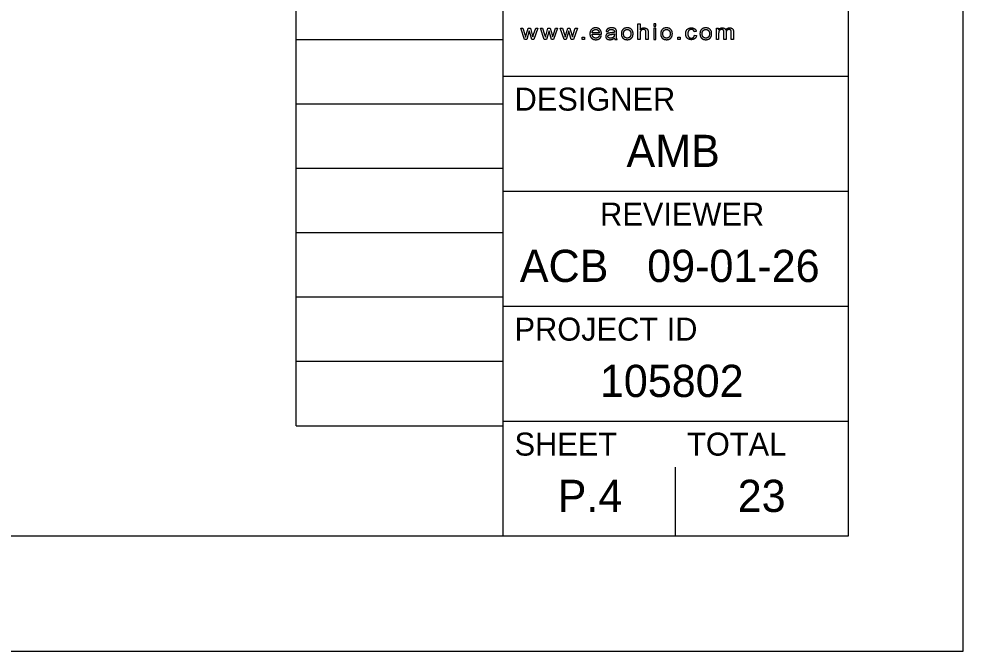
# Model space of a CAD drawing. Extents: x 0 to 34, y 0 to 22.
# Drawn here: x 29.895 to 34, y 0 to 2.749 of the extents above; entities that cross this region are included whole.
import ezdxf

# ---------------------------------------------------------------- set-up
doc = ezdxf.new("R2010")
doc.units = 0
for name, color, linetype in [('SH_Border', 7, 'Continuous'), ('SH_Cut_Line', 7, 'Continuous'), ('SH_Data', 7, 'Continuous'), ('TX_X_20', 7, 'Continuous')]:
    doc.layers.add(name, color=color, linetype=linetype)

msp = doc.modelspace()

# ---------------------------------------------------------------- linework, layer by layer
at = {"layer": 'SH_Border'}
for p, q in [((32, 0.5), (32, 21.5)), ((32, 2.5), (33.5, 2.5)), ((32, 2), (33.5, 2)), ((32, 1.5), (33.5, 1.5)), ((32, 1), (33.5, 1))]:
    msp.add_line(p, q, dxfattribs=at)
msp.add_lwpolyline([(1.5, 21.5), (33.5, 21.5), (33.5, 0.5), (1.5, 0.5)], close=True, dxfattribs=at)
at = {"layer": 'SH_Cut_Line'}
msp.add_lwpolyline([(0, 0), (34, 0), (34, 22), (0, 22)], close=True, dxfattribs=at)
at = {"layer": 'SH_Data'}
for p, q in [((31.1, 0.98), (31.1, 21.14)), ((32, 0.98), (32, 21.14)), ((31.1, 2.66), (32, 2.66)), ((31.1, 2.38), (32, 2.38)), ((31.1, 2.1), (32, 2.1)), ((31.1, 1.82), (32, 1.82)), ((31.1, 1.54), (32, 1.54)), ((31.1, 1.26), (32, 1.26)), ((31.1, 0.98), (32, 0.98)), ((32.75, 0.5), (32.75, 0.8)), ((32.375, 0.675), (32.375, 0.675))]:
    msp.add_line(p, q, dxfattribs=at)
at = {"layer": 'TX_X_20'}
for p, q in [((32.387, 2.6821), (32.4274, 2.6821)), ((32.4178, 2.6889), (32.3875, 2.6889)), ((32.4272, 2.6744), (32.4177, 2.6755)), ((32.4477, 2.6948), (32.4567, 2.6937)), ((32.4838, 2.6843), (32.4838, 2.6812)), ((32.4931, 2.6802), (32.4931, 2.6913)), ((32.5143, 2.6842), (32.5143, 2.6842)), ((32.5238, 2.6842), (32.5238, 2.6842)), ((32.6852, 2.6842), (32.6852, 2.6842)), ((32.6946, 2.6842), (32.6946, 2.6842)), ((32.8402, 2.6944), (32.8313, 2.6931)), ((32.8321, 2.6776), (32.8411, 2.6765)), ((32.856, 2.6842), (32.856, 2.6842)), ((32.8655, 2.6842), (32.8655, 2.6842)), ((32.4846, 2.6656), (32.4846, 2.6656)), ((32.4864, 2.6596), (32.496, 2.6596))]:
    msp.add_line(p, q, dxfattribs=at)
for points in [[(32.5955, 2.6865), (32.5955, 2.6596), (32.5863, 2.6596), (32.5863, 2.7276), (32.5955, 2.7276), (32.5955, 2.7032)], [(32.1007, 2.68), (32.1093, 2.7089), (32.1188, 2.7089), (32.1269, 2.6802), (32.1295, 2.6708), (32.1327, 2.6804), (32.142, 2.7089), (32.1509, 2.7089), (32.1339, 2.6596), (32.1244, 2.6596), (32.1158, 2.6891), (32.1137, 2.6975), (32.1027, 2.6596), (32.0931, 2.6596), (32.0766, 2.7089), (32.0861, 2.7089), (32.0947, 2.6804), (32.0979, 2.6698)], [(32.1867, 2.68), (32.1953, 2.7089), (32.2048, 2.7089), (32.2129, 2.6802), (32.2155, 2.6708), (32.2186, 2.6804), (32.228, 2.7089), (32.2369, 2.7089), (32.2199, 2.6596), (32.2104, 2.6596), (32.2018, 2.6891), (32.1997, 2.6975), (32.1886, 2.6596), (32.179, 2.6596), (32.1625, 2.7089), (32.172, 2.7089), (32.1807, 2.6804), (32.1838, 2.6698)], [(32.2726, 2.68), (32.2813, 2.7089), (32.2907, 2.7089), (32.2988, 2.6802), (32.3015, 2.6708), (32.3046, 2.6804), (32.3139, 2.7089), (32.3229, 2.7089), (32.3059, 2.6596), (32.2964, 2.6596), (32.2878, 2.6891), (32.2856, 2.6975), (32.2746, 2.6596), (32.265, 2.6596), (32.2485, 2.7089), (32.258, 2.7089), (32.2666, 2.6804), (32.2698, 2.6698)], [(32.6305, 2.6908), (32.6305, 2.6596), (32.6213, 2.6596), (32.6213, 2.6908)], [(32.9372, 2.6851), (32.9372, 2.6596), (32.928, 2.6596), (32.928, 2.7089), (32.9362, 2.7089), (32.9362, 2.7019)], [(32.9694, 2.6882), (32.9694, 2.6596), (32.9602, 2.6596), (32.9602, 2.6916)], [(33.0015, 2.6934), (33.0015, 2.6596), (32.9923, 2.6596), (32.9923, 2.6906)]]:
    msp.add_lwpolyline(points, dxfattribs=at)
for points in [[(32.655, 2.718), (32.6642, 2.718), (32.6642, 2.7276), (32.655, 2.7276)], [(32.3437, 2.6596), (32.3437, 2.669), (32.3541, 2.669), (32.3541, 2.6596)], [(32.655, 2.6596), (32.6642, 2.6596), (32.6642, 2.7089), (32.655, 2.7089)], [(32.7597, 2.6596), (32.7597, 2.669), (32.7702, 2.669), (32.7702, 2.6596)]]:
    msp.add_lwpolyline(points, close=True, dxfattribs=at)
for points in [[(32.4028, 2.71), (32.3916, 2.71), (32.3846, 2.7031)], [(32.4206, 2.7032), (32.4137, 2.71), (32.4028, 2.71)], [(32.4721, 2.71), (32.4651, 2.71), (32.4598, 2.7082)], [(32.4834, 2.7085), (32.479, 2.71), (32.4721, 2.71)], [(32.5398, 2.71), (32.5297, 2.71), (32.5227, 2.7045)], [(32.558, 2.7033), (32.5509, 2.71), (32.5398, 2.71)], [(32.5955, 2.7032), (32.602, 2.71), (32.6118, 2.71)], [(32.6118, 2.71), (32.6178, 2.71), (32.6222, 2.7078)], [(32.7106, 2.71), (32.7005, 2.71), (32.6935, 2.7045)], [(32.7288, 2.7033), (32.7218, 2.71), (32.7106, 2.71)], [(32.8056, 2.707), (32.8116, 2.71), (32.8186, 2.71)], [(32.8186, 2.71), (32.8274, 2.71), (32.833, 2.7059)], [(32.8814, 2.71), (32.8714, 2.71), (32.8644, 2.7045)], [(32.8997, 2.7033), (32.8926, 2.71), (32.8814, 2.71)], [(32.943, 2.7077), (32.9472, 2.71), (32.9527, 2.71)], [(32.9527, 2.71), (32.9587, 2.71), (32.9625, 2.7077)], [(32.968, 2.7013), (32.9744, 2.71), (32.9847, 2.71)], [(32.9847, 2.71), (32.9928, 2.71), (32.9972, 2.7059)], [(32.0979, 2.6698), (32.0981, 2.6706), (32.1007, 2.68)], [(32.1838, 2.6698), (32.184, 2.6706), (32.1867, 2.68)], [(32.2698, 2.6698), (32.27, 2.6706), (32.2726, 2.68)], [(32.3846, 2.7031), (32.3775, 2.6962), (32.3775, 2.6838)], [(32.3775, 2.6838), (32.3775, 2.6718), (32.3845, 2.6651)], [(32.3921, 2.6696), (32.3875, 2.6739), (32.387, 2.6821)], [(32.3875, 2.6889), (32.388, 2.6954), (32.3923, 2.6992)], [(32.4034, 2.6653), (32.3966, 2.6653), (32.3921, 2.6696)], [(32.3923, 2.6992), (32.3966, 2.7031), (32.4029, 2.7031)], [(32.4029, 2.7031), (32.4099, 2.7031), (32.4143, 2.6983)], [(32.4177, 2.6755), (32.4156, 2.6702), (32.412, 2.6677)], [(32.4143, 2.6983), (32.4172, 2.6951), (32.4178, 2.6889)], [(32.4189, 2.6626), (32.4249, 2.6668), (32.4272, 2.6744)], [(32.4275, 2.6843), (32.4275, 2.6965), (32.4206, 2.7032)], [(32.4274, 2.6821), (32.4275, 2.6835), (32.4275, 2.6843)], [(32.4479, 2.6792), (32.4461, 2.6762), (32.4461, 2.6726)], [(32.4461, 2.6726), (32.4461, 2.6664), (32.4509, 2.6624)], [(32.4517, 2.7032), (32.4489, 2.7), (32.4477, 2.6948)], [(32.4526, 2.684), (32.4497, 2.6822), (32.4479, 2.6792)], [(32.4598, 2.7082), (32.4545, 2.7065), (32.4517, 2.7032)], [(32.4592, 2.6867), (32.4555, 2.6858), (32.4526, 2.684)], [(32.4559, 2.6728), (32.4559, 2.675), (32.4571, 2.6768)], [(32.4586, 2.6672), (32.4559, 2.6695), (32.4559, 2.6728)], [(32.4567, 2.6937), (32.4581, 2.6989), (32.4612, 2.701)], [(32.4571, 2.6768), (32.4584, 2.6785), (32.4608, 2.6795)], [(32.4674, 2.688), (32.4619, 2.6873), (32.4592, 2.6867)], [(32.4608, 2.6795), (32.4631, 2.6804), (32.4688, 2.6811)], [(32.4612, 2.701), (32.4643, 2.7031), (32.4708, 2.7031)], [(32.4838, 2.6908), (32.4785, 2.6892), (32.4674, 2.688)], [(32.4688, 2.6811), (32.4788, 2.6824), (32.4838, 2.6843)], [(32.4708, 2.7031), (32.4777, 2.7031), (32.4812, 2.7002)], [(32.4823, 2.6729), (32.4803, 2.6692), (32.4762, 2.6671)], [(32.4812, 2.7002), (32.4838, 2.6981), (32.4838, 2.693)], [(32.4838, 2.6812), (32.4838, 2.6757), (32.4823, 2.6729)], [(32.4897, 2.7047), (32.4877, 2.707), (32.4834, 2.7085)], [(32.4838, 2.693), (32.4838, 2.6925), (32.4838, 2.6908)], [(32.4926, 2.699), (32.4918, 2.7025), (32.4897, 2.7047)], [(32.4931, 2.6913), (32.4931, 2.6969), (32.4926, 2.699)], [(32.4936, 2.6655), (32.4931, 2.6686), (32.4931, 2.6802)], [(32.5227, 2.7045), (32.5143, 2.6979), (32.5143, 2.6842)], [(32.5143, 2.6842), (32.5143, 2.6717), (32.5214, 2.6651)], [(32.5238, 2.6842), (32.5238, 2.6937), (32.5283, 2.6984)], [(32.5283, 2.67), (32.5238, 2.6747), (32.5238, 2.6842)], [(32.5283, 2.6984), (32.5329, 2.7031), (32.5398, 2.7031)], [(32.5398, 2.6653), (32.5329, 2.6653), (32.5283, 2.67)], [(32.5398, 2.7031), (32.5465, 2.7031), (32.5511, 2.6983)], [(32.5511, 2.6701), (32.5466, 2.6653), (32.5398, 2.6653)], [(32.5511, 2.6983), (32.5556, 2.6936), (32.5556, 2.6845)], [(32.5556, 2.6845), (32.5556, 2.6748), (32.5511, 2.6701)], [(32.5528, 2.6615), (32.5588, 2.6645), (32.562, 2.67)], [(32.5651, 2.6849), (32.5651, 2.6966), (32.558, 2.7033)], [(32.562, 2.67), (32.5651, 2.6754), (32.5651, 2.6849)], [(32.5971, 2.6956), (32.5955, 2.6923), (32.5955, 2.6865)], [(32.6022, 2.7008), (32.5986, 2.6989), (32.5971, 2.6956)], [(32.6099, 2.7028), (32.6058, 2.7028), (32.6022, 2.7008)], [(32.6183, 2.6999), (32.6153, 2.7028), (32.6099, 2.7028)], [(32.6213, 2.6908), (32.6213, 2.697), (32.6183, 2.6999)], [(32.6222, 2.7078), (32.6267, 2.7056), (32.6286, 2.7018)], [(32.6286, 2.7018), (32.6305, 2.698), (32.6305, 2.6908)], [(32.6935, 2.7045), (32.6852, 2.6979), (32.6852, 2.6842)], [(32.6852, 2.6842), (32.6852, 2.6717), (32.6922, 2.6651)], [(32.6946, 2.6842), (32.6946, 2.6937), (32.6992, 2.6984)], [(32.6992, 2.67), (32.6946, 2.6747), (32.6946, 2.6842)], [(32.6992, 2.6984), (32.7037, 2.7031), (32.7106, 2.7031)], [(32.7106, 2.6653), (32.7037, 2.6653), (32.6992, 2.67)], [(32.7106, 2.7031), (32.7174, 2.7031), (32.7219, 2.6983)], [(32.7219, 2.6701), (32.7174, 2.6653), (32.7106, 2.6653)], [(32.7219, 2.6983), (32.7265, 2.6936), (32.7265, 2.6845)], [(32.7265, 2.6845), (32.7265, 2.6748), (32.7219, 2.6701)], [(32.7237, 2.6615), (32.7297, 2.6645), (32.7328, 2.67)], [(32.7359, 2.6849), (32.7359, 2.6966), (32.7288, 2.7033)], [(32.7328, 2.67), (32.7359, 2.6754), (32.7359, 2.6849)], [(32.7939, 2.684), (32.7939, 2.692), (32.7968, 2.698)], [(32.8006, 2.6651), (32.7939, 2.6717), (32.7939, 2.684)], [(32.7968, 2.698), (32.7997, 2.704), (32.8056, 2.707)], [(32.8077, 2.6986), (32.8033, 2.6941), (32.8033, 2.6843)], [(32.8033, 2.6843), (32.8033, 2.6743), (32.8075, 2.6698)], [(32.8075, 2.6698), (32.8117, 2.6653), (32.8185, 2.6653)], [(32.8189, 2.7031), (32.812, 2.7031), (32.8077, 2.6986)], [(32.8185, 2.6653), (32.8239, 2.6653), (32.8275, 2.6683)], [(32.8268, 2.7006), (32.8235, 2.7031), (32.8189, 2.7031)], [(32.8313, 2.6931), (32.83, 2.6981), (32.8268, 2.7006)], [(32.8275, 2.6683), (32.8311, 2.6713), (32.8321, 2.6776)], [(32.833, 2.7059), (32.8387, 2.7018), (32.8402, 2.6944)], [(32.8411, 2.6765), (32.8396, 2.668), (32.8335, 2.6633)], [(32.8644, 2.7045), (32.856, 2.6979), (32.856, 2.6842)], [(32.856, 2.6842), (32.856, 2.6717), (32.863, 2.6651)], [(32.8655, 2.6842), (32.8655, 2.6937), (32.87, 2.6984)], [(32.87, 2.67), (32.8655, 2.6747), (32.8655, 2.6842)], [(32.87, 2.6984), (32.8745, 2.7031), (32.8814, 2.7031)], [(32.8814, 2.6653), (32.8745, 2.6653), (32.87, 2.67)], [(32.8814, 2.7031), (32.8882, 2.7031), (32.8927, 2.6983)], [(32.8928, 2.6701), (32.8882, 2.6653), (32.8814, 2.6653)], [(32.8927, 2.6983), (32.8973, 2.6936), (32.8973, 2.6845)], [(32.8973, 2.6845), (32.8973, 2.6748), (32.8928, 2.6701)], [(32.8945, 2.6615), (32.9005, 2.6645), (32.9036, 2.67)], [(32.9068, 2.6849), (32.9068, 2.6966), (32.8997, 2.7033)], [(32.9036, 2.67), (32.9068, 2.6754), (32.9068, 2.6849)], [(32.9362, 2.7019), (32.9388, 2.7055), (32.943, 2.7077)], [(32.9387, 2.6954), (32.9372, 2.6918), (32.9372, 2.6851)], [(32.9434, 2.7008), (32.9401, 2.699), (32.9387, 2.6954)], [(32.9506, 2.7027), (32.9467, 2.7027), (32.9434, 2.7008)], [(32.958, 2.6999), (32.9557, 2.7027), (32.9506, 2.7027)], [(32.9602, 2.6916), (32.9602, 2.6971), (32.958, 2.6999)], [(32.9625, 2.7077), (32.9664, 2.7054), (32.968, 2.7013)], [(32.9732, 2.6992), (32.9694, 2.6958), (32.9694, 2.6882)], [(32.9827, 2.7027), (32.977, 2.7027), (32.9732, 2.6992)], [(32.9882, 2.7014), (32.9858, 2.7027), (32.9827, 2.7027)], [(32.9914, 2.6978), (32.9905, 2.7), (32.9882, 2.7014)], [(32.9923, 2.6906), (32.9923, 2.6956), (32.9914, 2.6978)], [(32.9972, 2.7059), (33.0015, 2.7018), (33.0015, 2.6934)], [(32.3845, 2.6651), (32.3915, 2.6585), (32.4034, 2.6585)], [(32.412, 2.6677), (32.4085, 2.6653), (32.4034, 2.6653)], [(32.4034, 2.6585), (32.4128, 2.6585), (32.4189, 2.6626)], [(32.4509, 2.6624), (32.4556, 2.6585), (32.4646, 2.6585)], [(32.4668, 2.665), (32.4614, 2.665), (32.4586, 2.6672)], [(32.4646, 2.6585), (32.47, 2.6585), (32.4747, 2.6601)], [(32.4762, 2.6671), (32.4721, 2.665), (32.4668, 2.665)], [(32.4747, 2.6601), (32.4794, 2.6617), (32.4846, 2.6656)], [(32.4846, 2.6656), (32.485, 2.6622), (32.4864, 2.6596)], [(32.496, 2.6596), (32.4942, 2.6624), (32.4936, 2.6655)], [(32.5214, 2.6651), (32.5284, 2.6585), (32.5398, 2.6585)], [(32.5398, 2.6585), (32.5468, 2.6585), (32.5528, 2.6615)], [(32.6922, 2.6651), (32.6992, 2.6585), (32.7106, 2.6585)], [(32.7106, 2.6585), (32.7177, 2.6585), (32.7237, 2.6615)], [(32.8185, 2.6585), (32.8074, 2.6585), (32.8006, 2.6651)], [(32.8335, 2.6633), (32.8274, 2.6585), (32.8185, 2.6585)], [(32.863, 2.6651), (32.87, 2.6585), (32.8814, 2.6585)], [(32.8814, 2.6585), (32.8885, 2.6585), (32.8945, 2.6615)]]:
    msp.add_open_spline(points, degree=2, dxfattribs=at)

# ---------------------------------------------------------------- texts
at = {"layer": 'SH_Data'}
for s, height, p in [('DESIGNER', 0.1, (32.05, 2.35)), ('AMB', 0.14, (32.5366, 2.105)), ('REVIEWER', 0.1, (32.4218, 1.85)), ('ACB', 0.14, (32.0729, 1.605)), ('09-01-26', 0.14, (32.6266, 1.605)), ('PROJECT ID', 0.1, (32.05, 1.35)), ('105802', 0.14, (32.4209, 1.105)), ('SHEET', 0.1, (32.05, 0.85)), ('TOTAL', 0.1, (32.8, 0.85)), ('P.4', 0.14, (32.2374, 0.605)), ('23', 0.14, (33.02, 0.605))]:
    msp.add_text(s, height=height, dxfattribs=at).set_placement(p)

doc.saveas('drawing.dxf')
